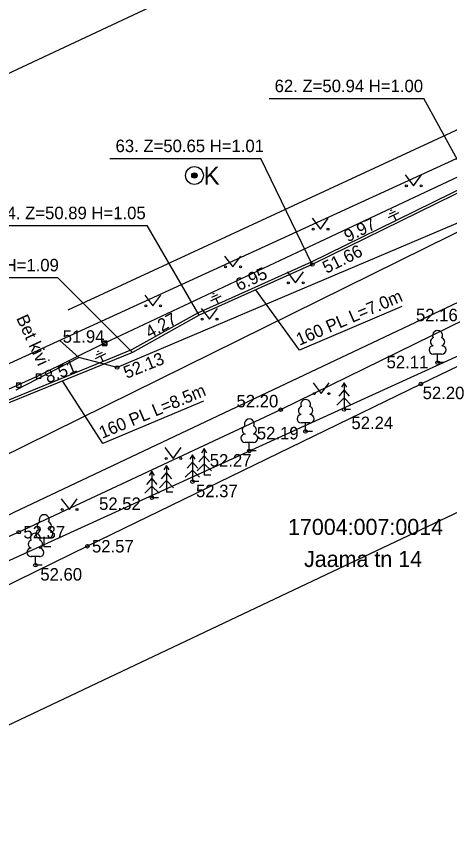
# Model space of a CAD drawing. Extents: x 642747 to 644424, y 6457048 to 6458238.
# Drawn here: x 643760.23 to 643784.56, y 6457535.1 to 6457580.58 of the extents above; entities that cross this region are included whole.
import ezdxf

# ---------------------------------------------------------------- set-up
doc = ezdxf.new("R2010")
doc.units = 0
for name, color, linetype in [('ABIJOONIS', 7, 'Continuous'), ('AED', 7, 'Continuous'), ('HALJASTUS', 7, 'Continuous'), ('JOONSIDE', 7, 'Continuous'), ('KOORDPUNKT', 7, 'Continuous'), ('KORGUS', 7, 'Continuous'), ('KPKAABEL', 7, 'Continuous'), ('MOOTPIIR', 7, 'Continuous'), ('MPKAABEL', 7, 'Continuous'), ('PIIR', 7, 'Continuous'), ('PUU', 7, 'Continuous'), ('SITRASS', 7, 'Continuous'), ('TEE', 7, 'Continuous'), ('VKAEV', 7, 'Continuous')]:
    doc.layers.add(name, color=color, linetype=linetype)

msp = doc.modelspace()

# ---------------------------------------------------------------- linework, layer by layer
at = {"layer": 'ABIJOONIS'}
for points in [[(643781.871, 6457564.293), (643776.131, 6457561.839), (643773.671, 6457565.22)], [(643770.737, 6457558.973), (643765.101, 6457556.598), (643762.822, 6457560.115)]]:
    msp.add_lwpolyline(points, dxfattribs=at)
at = {"layer": 'AED'}
for p, q in [((643765.06, 6457562.36), (643765.06, 6457562.11)), ((643765.06, 6457562.36), (643765.31, 6457562.36)), ((643765.06, 6457562.11), (643765.31, 6457562.11)), ((643765.31, 6457562.36), (643765.31, 6457562.11)), ((643761.359, 6457560.522), (643761.359, 6457560.272)), ((643761.359, 6457560.522), (643761.609, 6457560.522)), ((643761.359, 6457560.272), (643761.609, 6457560.272)), ((643761.609, 6457560.522), (643761.609, 6457560.272)), ((643760.242, 6457560.012), (643760.242, 6457559.762)), ((643760.242, 6457560.012), (643760.492, 6457560.012)), ((643760.242, 6457559.762), (643760.492, 6457559.762)), ((643760.492, 6457560.012), (643760.492, 6457559.762))]:
    msp.add_line(p, q, dxfattribs=at)
for points in [[(643791.994, 6457610.578), (643806.741, 6457581.864), (643790.954, 6457574.348), (643777.275, 6457567.918), (643765.185, 6457562.235), (643761.484, 6457560.397), (643760.367, 6457559.887)], [(643805.045, 6457570.599), (643782.93, 6457559.942), (643764.223, 6457550.839), (643748.509, 6457543.138), (643744.061, 6457541.111), (643730.468, 6457534.795)], [(643760.367, 6457559.887), (643737.039, 6457549.403), (643734.901, 6457553.784), (643731.617, 6457560.816), (643731.187, 6457561.684), (643727.719, 6457568.92)]]:
    msp.add_lwpolyline(points, dxfattribs=at)
at = {"layer": 'HALJASTUS'}
for p, q in [((643802.831, 6457582.491), (643763.12, 6457564.079)), ((643782.057, 6457571.673), (643782.52, 6457571.067)), ((643782.52, 6457571.067), (643782.966, 6457571.673)), ((643776.833, 6457569.239), (643777.297, 6457568.633)), ((643777.297, 6457568.633), (643777.742, 6457569.239)), ((643771.918, 6457567.117), (643772.381, 6457566.511)), ((643772.381, 6457566.511), (643772.826, 6457567.117)), ((643775.437, 6457566.229), (643775.9, 6457565.623)), ((643775.9, 6457565.623), (643776.346, 6457566.229)), ((643767.442, 6457564.933), (643767.906, 6457564.327)), ((643767.906, 6457564.327), (643768.351, 6457564.933)), ((643770.607, 6457564.182), (643771.07, 6457563.575)), ((643771.07, 6457563.575), (643771.516, 6457564.182)), ((643776.885, 6457560.008), (643777.349, 6457559.401)), ((643777.349, 6457559.401), (643777.794, 6457560.008)), ((643768.576, 6457556.376), (643769.04, 6457555.77)), ((643769.04, 6457555.77), (643769.485, 6457556.376)), ((643762.751, 6457553.509), (643763.214, 6457552.903)), ((643763.214, 6457552.903), (643763.66, 6457553.509))]:
    msp.add_line(p, q, dxfattribs=at)
for centre in [(643782.119, 6457571.067), (643782.948, 6457571.067), (643776.895, 6457568.633), (643777.724, 6457568.633), (643771.98, 6457566.511), (643772.809, 6457566.511), (643775.499, 6457565.623), (643776.328, 6457565.623), (643767.505, 6457564.327), (643768.334, 6457564.327), (643770.669, 6457563.575), (643771.498, 6457563.575), (643776.948, 6457559.401), (643777.777, 6457559.401), (643768.639, 6457555.77), (643769.468, 6457555.77), (643762.813, 6457552.903), (643763.642, 6457552.903)]:
    msp.add_circle(centre, 0.055, dxfattribs=at)
at = {"layer": 'KOORDPUNKT'}
for p, q in [((643774.416, 6457575.968), (643783.095, 6457575.968)), ((643785.796, 6457571.037), (643783.095, 6457575.968)), ((643765.491, 6457572.604), (643773.96, 6457572.604)), ((643776.843, 6457566.645), (643773.96, 6457572.604)), ((643758.856, 6457568.841), (643767.571, 6457568.841)), ((643770.499, 6457563.796), (643767.571, 6457568.841)), ((643753.983, 6457565.913), (643762.557, 6457565.913)), ((643766.764, 6457561.718), (643762.557, 6457565.913))]:
    msp.add_line(p, q, dxfattribs=at)
for points in [[(643776.843, 6457566.645), (643776.843, 6457566.645), (643776.843, 6457566.645)], [(643770.499, 6457563.796), (643770.499, 6457563.796), (643770.499, 6457563.796)], [(643766.764, 6457561.718), (643766.764, 6457561.718), (643766.764, 6457561.718)]]:
    msp.add_lwpolyline(points, dxfattribs=at)
at = {"layer": 'KORGUS'}
for centre in [(643770.231, 6457571.641), (643776.843, 6457566.645), (643765.185, 6457562.235), (643783.871, 6457561.143), (643765.892, 6457560.87), (643782.93, 6457559.942), (643775.068, 6457558.5), (643778.623, 6457558.514), (643776.466, 6457557.282), (643773.31, 6457556.185), (643770.12, 6457554.466), (643767.849, 6457553.559), (643760.375, 6457551.627), (643764.223, 6457550.839), (643761.31, 6457549.78)]:
    msp.add_circle(centre, 0.1, dxfattribs=at)
at = {"layer": 'KPKAABEL'}
for points in [[(643785.796, 6457571.037), (643776.843, 6457566.645), (643770.499, 6457563.796), (643766.764, 6457561.718), (643758.879, 6457558.513), (643750.579, 6457554.536), (643740.363, 6457549.55), (643737.514, 6457548.159), (643731.518, 6457545.231), (643723.365, 6457541.248), (643714.481, 6457536.971), (643704.897, 6457532.652), (643697.084, 6457528.238), (643696.229, 6457527.748), (643694.912, 6457530.116), (643695.681, 6457530.934)], [(643776.843, 6457566.645), (643770.499, 6457563.796)], [(643766.764, 6457561.718), (643758.879, 6457558.513)]]:
    msp.add_lwpolyline(points, dxfattribs=at)
at = {"layer": 'MOOTPIIR'}
msp.add_lwpolyline([(643525.446, 6457467.559), (643537.447, 6457435.458), (643944.848, 6457628.51), (644046.626, 6457529.09), (644067.022, 6457529.09), (644138.408, 6457598.401), (644075.1, 6457775.215), (644046.02, 6457752.582), (644092.466, 6457611.94), (644070.657, 6457576.375), (644041.981, 6457570.717), (643942.223, 6457662.862)], close=True, dxfattribs=at)
at = {"layer": 'MPKAABEL'}
for points in [[(643805.865, 6457580.432), (643796.279, 6457575.688), (643787.981, 6457572.136), (643785.733, 6457571.173), (643781.554, 6457569.123), (643776.779, 6457566.78), (643771.586, 6457564.448), (643770.432, 6457563.93), (643766.699, 6457561.854), (643765.114, 6457561.209), (643758.818, 6457558.65), (643756.401, 6457557.492), (643747.057, 6457552.984), (643738.225, 6457548.673), (643729.558, 6457544.44), (643720.951, 6457540.252), (643713.648, 6457536.761), (643705.623, 6457533.144), (643700.531, 6457529.783), (643697.449, 6457528.309), (643696.488, 6457530.191)], [(643781.121, 6457569.291), (643781.694, 6457569.566)], [(643781.177, 6457569.485), (643781.508, 6457569.644)], [(643781.233, 6457569.678), (643781.323, 6457569.721)], [(643781.554, 6457569.123), (643781.408, 6457569.429)], [(643771.153, 6457564.616), (643771.726, 6457564.891)], [(643771.209, 6457564.809), (643771.54, 6457564.969)], [(643771.264, 6457565.003), (643771.355, 6457565.046)], [(643771.586, 6457564.448), (643771.439, 6457564.754)], [(643764.681, 6457561.377), (643765.254, 6457561.652)], [(643764.737, 6457561.571), (643765.068, 6457561.73)], [(643764.792, 6457561.764), (643764.883, 6457561.807)], [(643765.114, 6457561.209), (643764.967, 6457561.515)]]:
    msp.add_lwpolyline(points, dxfattribs=at)
at = {"layer": 'PIIR'}
for points in [[(643807.33, 6457582.88), (643742.37, 6457711.12), (643680.23, 6457682.19), (643708.95, 6457623.53), (643648.6, 6457595.3), (643683.74, 6457526.24)], [(643830.56, 6457531.4), (643810.31, 6457573.05), (643747.54, 6457544.43), (643768.96, 6457500.48)]]:
    msp.add_lwpolyline(points, close=True, dxfattribs=at)
at = {"layer": 'PUU'}
for p, q in [((643784.111, 6457561.618), (643783.631, 6457561.618)), ((643783.871, 6457561.143), (643783.871, 6457561.618)), ((643784.251, 6457561.143), (643783.871, 6457561.143)), ((643778.623, 6457560.014), (643778.473, 6457559.764)), ((643778.773, 6457559.764), (643778.623, 6457560.014)), ((643778.623, 6457560.014), (643778.623, 6457558.514)), ((643778.623, 6457559.614), (643778.323, 6457559.264)), ((643778.923, 6457559.264), (643778.623, 6457559.614)), ((643778.623, 6457559.164), (643778.223, 6457558.764)), ((643779.023, 6457558.764), (643778.623, 6457559.164)), ((643778.983, 6457558.514), (643778.623, 6457558.514)), ((643776.706, 6457557.757), (643776.226, 6457557.757)), ((643776.466, 6457557.282), (643776.466, 6457557.757)), ((643776.846, 6457557.282), (643776.466, 6457557.282)), ((643773.55, 6457556.66), (643773.07, 6457556.66)), ((643773.31, 6457556.185), (643773.31, 6457556.66)), ((643770.784, 6457556.319), (643770.634, 6457556.069)), ((643770.934, 6457556.069), (643770.784, 6457556.319)), ((643770.784, 6457556.319), (643770.784, 6457554.819)), ((643773.69, 6457556.185), (643773.31, 6457556.185)), ((643770.12, 6457555.966), (643769.97, 6457555.716)), ((643770.27, 6457555.716), (643770.12, 6457555.966)), ((643770.12, 6457555.966), (643770.12, 6457554.466)), ((643770.784, 6457555.919), (643770.484, 6457555.569)), ((643771.084, 6457555.569), (643770.784, 6457555.919)), ((643768.663, 6457555.369), (643768.513, 6457555.119)), ((643768.813, 6457555.119), (643768.663, 6457555.369)), ((643768.663, 6457555.369), (643768.663, 6457553.869)), ((643770.12, 6457555.566), (643769.82, 6457555.216)), ((643770.42, 6457555.216), (643770.12, 6457555.566)), ((643770.784, 6457555.469), (643770.384, 6457555.069)), ((643771.184, 6457555.069), (643770.784, 6457555.469)), ((643767.849, 6457555.059), (643767.699, 6457554.809)), ((643767.999, 6457554.809), (643767.849, 6457555.059)), ((643767.849, 6457555.059), (643767.849, 6457553.559)), ((643768.663, 6457554.969), (643768.363, 6457554.619)), ((643768.963, 6457554.619), (643768.663, 6457554.969)), ((643770.12, 6457555.116), (643769.72, 6457554.716)), ((643770.52, 6457554.716), (643770.12, 6457555.116)), ((643771.144, 6457554.819), (643770.784, 6457554.819)), ((643767.849, 6457554.659), (643767.549, 6457554.309)), ((643768.149, 6457554.309), (643767.849, 6457554.659)), ((643768.663, 6457554.519), (643768.263, 6457554.119)), ((643769.063, 6457554.119), (643768.663, 6457554.519)), ((643770.48, 6457554.466), (643770.12, 6457554.466)), ((643767.849, 6457554.209), (643767.449, 6457553.809)), ((643768.249, 6457553.809), (643767.849, 6457554.209)), ((643769.023, 6457553.869), (643768.663, 6457553.869)), ((643768.209, 6457553.559), (643767.849, 6457553.559)), ((643762.042, 6457551.289), (643761.562, 6457551.289)), ((643761.802, 6457550.814), (643761.802, 6457551.289)), ((643762.182, 6457550.814), (643761.802, 6457550.814)), ((643761.55, 6457550.255), (643761.07, 6457550.255)), ((643761.31, 6457549.78), (643761.31, 6457550.255)), ((643761.69, 6457549.78), (643761.31, 6457549.78))]:
    msp.add_line(p, q, dxfattribs=at)
for centre, radius, start, end in [((643783.871, 6457562.663), 0.277, 332.5799, 207.4201), ((643783.701, 6457562.315), 0.233, 109.0217, 253.1415), ((643784.041, 6457562.315), 0.233, 286.8508, 70.9859), ((643783.633, 6457561.855), 0.238, 90.0016, 269.3953), ((643784.108, 6457561.855), 0.238, 270.6047, 89.9984), ((643776.466, 6457558.802), 0.277, 332.5799, 207.4201), ((643776.296, 6457558.454), 0.233, 109.0217, 253.1415), ((643776.636, 6457558.454), 0.233, 286.8508, 70.9859), ((643773.31, 6457557.705), 0.277, 332.5799, 207.4201), ((643776.228, 6457557.994), 0.238, 90.0016, 269.3953), ((643776.703, 6457557.994), 0.238, 270.6047, 89.9984), ((643773.14, 6457557.357), 0.233, 109.0217, 253.1415), ((643773.48, 6457557.357), 0.233, 286.8508, 70.9859), ((643773.073, 6457556.897), 0.238, 90.0016, 269.3953), ((643773.548, 6457556.897), 0.238, 270.6047, 89.9984), ((643761.802, 6457552.334), 0.277, 332.5799, 207.4201), ((643761.632, 6457551.986), 0.233, 109.0217, 253.1415), ((643761.972, 6457551.986), 0.233, 286.8508, 70.9859), ((643761.31, 6457551.3), 0.277, 332.5799, 207.4201), ((643761.565, 6457551.526), 0.238, 90.0016, 269.3953), ((643762.04, 6457551.526), 0.238, 270.6047, 89.9984), ((643761.14, 6457550.952), 0.233, 109.0217, 253.1415), ((643761.48, 6457550.952), 0.233, 286.8508, 70.9859), ((643761.072, 6457550.492), 0.238, 90.0016, 269.3953), ((643761.547, 6457550.492), 0.238, 270.6047, 89.9984)]:
    msp.add_arc(centre, radius, start, end, dxfattribs=at)
at = {"layer": 'SITRASS'}
msp.add_lwpolyline([(643814.156, 6457570.25), (643811.349, 6457574.393), (643810.727, 6457574.717), (643809.889, 6457574.858), (643799.015, 6457570.178), (643785.395, 6457563.561), (643775.068, 6457558.5), (643760.375, 6457551.627), (643746.716, 6457545.631), (643746.704, 6457544.802), (643746.702, 6457544.799), (643746.829, 6457544.323), (643746.616, 6457545.538), (643724.743, 6457535.187), (643710.503, 6457528.359), (643694.573, 6457521.224), (643694.552, 6457520.484), (643694.666, 6457520.025)], dxfattribs=at)
at = {"layer": 'TEE'}
for points in [[(643718.254, 6457535.466), (643742.796, 6457547.653), (643792.174, 6457572.021)], [(643792.174, 6457572.021), (643765.892, 6457560.87), (643763.742, 6457561.428), (643762.674, 6457562.391)], [(643601.811, 6457477.818), (643614.888, 6457484.225), (643629.926, 6457491.355), (643646.627, 6457498.988), (643663.305, 6457506.521), (643682.169, 6457515.373), (643702.706, 6457525.068), (643719.451, 6457532.981), (643744.189, 6457544.886), (643760.109, 6457552.753), (643794.075, 6457568.819)], [(643760.223, 6457559.615), (643763.742, 6457561.428)]]:
    msp.add_lwpolyline(points, dxfattribs=at)
at = {"layer": 'VKAEV'}
for radius in [0.5, 0.15, 0.125, 0.1, 0.075, 0.05, 0.025]:
    msp.add_circle((643770.231, 6457571.641), radius, dxfattribs=at)

# ---------------------------------------------------------------- texts
at = {"layer": 'ABIJOONIS'}
for s, rotation, p in [('160 PL L=7.0m', 23.378, (643776.121, 6457562.084)), ('160 PL L=8.5m', 22.7162, (643765.057, 6457556.863))]:
    msp.add_text(s, height=0.7, rotation=rotation, dxfattribs=at).set_placement(p)
at = {"layer": 'JOONSIDE'}
for s, rotation, p in [('9.97', 26.1341, (643778.841, 6457567.881)), ('6.95', 24.1857, (643772.725, 6457565.15)), ('4.27', 29.0828, (643767.723, 6457562.483)), ('8.51', 22.121, (643762.005, 6457559.968))]:
    msp.add_text(s, height=0.7, rotation=rotation, dxfattribs=at).set_placement(p)
at = {"layer": 'KOORDPUNKT'}
for s, p in [('62. Z=50.94 H=1.00', (643774.731, 6457576.318)), ('63. Z=50.65 H=1.01', (643765.806, 6457572.954)), ('64. Z=50.89 H=1.05', (643759.171, 6457569.191)), ('65. Z=51.01 H=1.09', (643754.298, 6457566.263))]:
    msp.add_text(s, height=0.7, dxfattribs=at).set_placement(p)
at = {"layer": 'KORGUS'}
for s, rotation, p in [('51.66', 26.5801, (643777.638, 6457566.12)), (' 52.13', 21.7094, (643766.183, 6457560.133))]:
    msp.add_text(s, height=0.7, rotation=rotation, dxfattribs=at).set_placement(p)
for s, p in [(' 52.16', (643782.401, 6457563.463)), (' 51.94', (643762.581, 6457562.259)), (' 52.11', (643780.752, 6457560.824)), (' 52.20', (643782.774, 6457559.092)), (' 52.20', (643772.332, 6457558.632)), (' 52.24', (643778.779, 6457557.412)), (' 52.19', (643773.472, 6457556.835)), (' 52.27', (643770.831, 6457555.309)), (' 52.37', (643770.058, 6457553.593)), (' 52.52', (643764.621, 6457552.876)), (' 52.37', (643760.375, 6457551.277)), (' 52.57', (643764.223, 6457550.489)), (' 52.60', (643761.325, 6457548.913))]:
    msp.add_text(s, height=0.7, dxfattribs=at).set_placement(p)
at = {"layer": 'PIIR'}
for s, p in [('17004:007:0014', (643775.48, 6457551.475)), ('Jaama tn 14', (643776.38, 6457549.675))]:
    msp.add_text(s, height=0.9, dxfattribs=at).set_placement(p)
at = {"layer": 'TEE'}
msp.add_text('Bet kivi', height=0.7, rotation=294.7283, dxfattribs=at).set_placement((643760.218, 6457563.638))
at = {"layer": 'VKAEV'}
msp.add_text('K', height=1, dxfattribs=at).set_placement((643770.747, 6457571.136))

doc.saveas('drawing.dxf')
